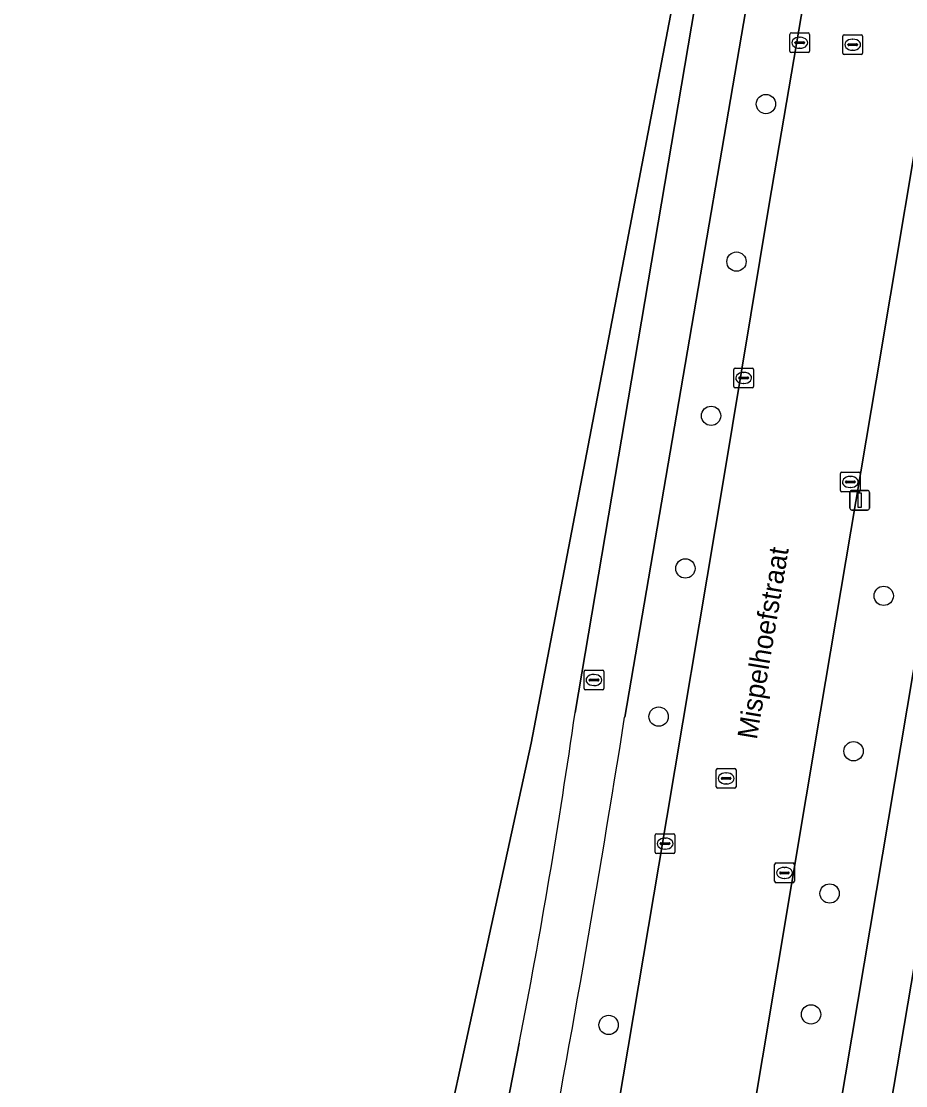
# Model space of a CAD drawing. Extents: x 156141 to 158132, y 385651 to 388333.
# Drawn here: x 156323 to 156367.7, y 386609.6 to 386663.4 of the extents above; entities that cross this region are included whole.
import ezdxf

# ---------------------------------------------------------------- set-up
doc = ezdxf.new("R2010")
doc.units = 0
for name, color, linetype in [('IMGEO_Berm_groen', 7, 'Continuous'), ('IMGEO_Boom', 7, 'Continuous'), ('IMGEO_Bouwland', 7, 'Continuous'), ('IMGEO_Fietspad_gesloten', 7, 'Continuous'), ('IMGEO_Kolk', 7, 'Continuous'), ('IMGEO_Lichtmast', 7, 'Continuous'), ('IMGEO_Openbare_ruimte_label', 7, 'Continuous'), ('IMGEO_Rijbaan_lokaal_gesloten', 7, 'Continuous'), ('IMGEO_Rioolput', 7, 'Continuous')]:
    doc.layers.add(name, color=color, linetype=linetype)

msp = doc.modelspace()

# ---------------------------------------------------------------- linework, layer by layer
at = {"layer": 'IMGEO_Berm_groen'}
for points in [[(156350.987, 386628.45), (156359.899, 386681.019), (156358.914, 386681.214), (156356.118, 386665.332), (156348.768, 386626.891), (156344.27, 386606.243), (156337.845, 386577.757), (156327.718, 386536.986), (156329.08, 386536.913), (156329.901, 386538.856), (156331.742, 386543.951), (156334.06, 386550.854), (156337.052, 386561.839), (156338.908, 386569.228), (156341.252, 386578.081), (156343.943, 386590.004), (156348.163, 386611.714)], [(156365.172, 386680.123), (156365.04, 386680.147), (156362.466, 386680.594), (156353.497, 386628.209)], [(156343.685, 386553.103), (156344.204, 386556.07), (156346.788, 386570.974), (156348.646, 386581.912), (156350.84, 386594.689), (156355.222, 386620.708), (156358.486, 386640.111), (156360.809, 386654.165), (156363.553, 386670.315), (156364.774, 386677.704), (156365.172, 386680.123)], [(156369.305, 386663.658), (156369.141, 386662.678), (156366.222, 386645.225), (156363.399, 386628.51), (156359.75, 386606.622), (156357.341, 386592.608), (156355.257, 386580.281), (156355.517, 386580.234), (156355.483, 386579.181), (156355.759, 386578.249), (156356.674, 386577.611), (156357.605, 386577.179), (156359.068, 386576.796), (156374.013, 386665.695)], [(156376.478, 386664.815), (156361.284, 386575.046)]]:
    msp.add_lwpolyline(points, dxfattribs=at)
for centre, radius, start, end in [((156028.231, 386674.305), 325.997, 348.93056, 351.91393), ((155545.833, 386756.054), 817.719, 349.208364, 351.005279)]:
    msp.add_arc(centre, radius, start, end, dxfattribs=at)
at = {"layer": 'IMGEO_Boom'}
for centre in [(156360.642, 386659.24), (156359.153, 386651.263), (156357.868, 386643.46), (156356.567, 386635.735), (156366.602, 386634.347), (156355.216, 386628.235), (156365.076, 386626.484), (156363.865, 386619.284), (156362.925, 386613.163), (156352.686, 386612.628)]:
    msp.add_circle(centre, 0.489, dxfattribs=at)
at = {"layer": 'IMGEO_Bouwland'}
msp.add_lwpolyline([(156327.718, 386536.986), (156337.845, 386577.757), (156344.27, 386606.243), (156348.768, 386626.891), (156356.118, 386665.332), (156358.914, 386681.214), (156359.797, 386685.773), (156360.143, 386687.587), (156357.465, 386688.104), (156352.633, 386690.072), (156333.91, 386700.028), (156319.754, 386708.223)], dxfattribs=at)
at = {"layer": 'IMGEO_Fietspad_gesloten'}
for points in [[(156364.735, 386706.911), (156361.044, 386687.413), (156360.703, 386685.612), (156359.899, 386681.019), (156350.987, 386628.45)], [(156353.497, 386628.209), (156362.466, 386680.594), (156363.223, 386685.205), (156367.269, 386706.451)], [(156377.323, 386685.122), (156376.063, 386677.545), (156374.013, 386665.695), (156359.068, 386576.796), (156358.828, 386575.366), (156357.806, 386569.203), (156357.464, 386566.853), (156356.663, 386561.356), (156354.926, 386551.515), (156354.742, 386549.567), (156354.24, 386545.154), (156354.117, 386544.788), (156353.91, 386544.661), (156353.548, 386544.638), (156353.12, 386544.854), (156352.234, 386545.713), (156351.908, 386546.133), (156351.166, 386547.177)], [(156360.26, 386568.995), (156361.284, 386575.046), (156376.478, 386664.815)], [(156348.163, 386611.714), (156343.943, 386590.004), (156341.252, 386578.081), (156338.908, 386569.228), (156337.052, 386561.839), (156334.06, 386550.854), (156331.742, 386543.951), (156329.901, 386538.856), (156329.08, 386536.913), (156328.367, 386535.225), (156326.447, 386529.996), (156325.935, 386528.385), (156324.936, 386524.744), (156324.596, 386523.924)]]:
    msp.add_lwpolyline(points, dxfattribs=at)
for centre, radius, start, end in [((156028.231, 386674.305), 325.997, 348.93056, 351.91393), ((155545.833, 386756.054), 817.719, 349.208364, 351.005279)]:
    msp.add_arc(centre, radius, start, end, dxfattribs=at)
at = {"layer": 'IMGEO_Kolk'}
for p, q in [((156361.929, 386662.841), (156362.781, 386662.841)), ((156361.854, 386661.915), (156361.854, 386662.767)), ((156362.113, 386662.335), (156362.113, 386662.347)), ((156362.551, 386662.298), (156362.153, 386662.298)), ((156362.156, 386662.384), (156362.554, 386662.384)), ((156362.342, 386662.621), (156362.367, 386662.621)), ((156362.597, 386662.347), (156362.597, 386662.335)), ((156362.855, 386662.767), (156362.855, 386661.915)), ((156362.781, 386661.841), (156361.929, 386661.841)), ((156362.365, 386662.061), (156362.34, 386662.061)), ((156359.016, 386644.949), (156359.016, 386645.801)), ((156359.091, 386645.875), (156359.943, 386645.875)), ((156359.504, 386645.655), (156359.529, 386645.655)), ((156360.017, 386645.801), (156360.017, 386644.949)), ((156359.275, 386645.369), (156359.275, 386645.381)), ((156359.713, 386645.332), (156359.315, 386645.332)), ((156359.318, 386645.418), (156359.716, 386645.418)), ((156359.527, 386645.095), (156359.502, 386645.095)), ((156359.759, 386645.381), (156359.759, 386645.369)), ((156359.943, 386644.875), (156359.091, 386644.875)), ((156364.412, 386639.685), (156364.412, 386640.537)), ((156364.487, 386640.611), (156365.339, 386640.611)), ((156364.9, 386640.391), (156364.925, 386640.391)), ((156365.413, 386640.537), (156365.413, 386639.685)), ((156364.671, 386640.105), (156364.671, 386640.117)), ((156365.109, 386640.068), (156364.711, 386640.068)), ((156364.714, 386640.154), (156365.112, 386640.154)), ((156364.923, 386639.831), (156364.898, 386639.831)), ((156365.155, 386640.117), (156365.155, 386640.105)), ((156365.339, 386639.611), (156364.487, 386639.611)), ((156355.041, 386621.38), (156355.041, 386622.232)), ((156355.116, 386622.306), (156355.968, 386622.306)), ((156355.529, 386622.086), (156355.554, 386622.086)), ((156356.042, 386622.232), (156356.042, 386621.38)), ((156355.3, 386621.8), (156355.3, 386621.812)), ((156355.738, 386621.763), (156355.34, 386621.763)), ((156355.343, 386621.849), (156355.741, 386621.849)), ((156355.552, 386621.526), (156355.527, 386621.526)), ((156355.784, 386621.812), (156355.784, 386621.8)), ((156355.968, 386621.306), (156355.116, 386621.306)), ((156361.154, 386620.826), (156362.006, 386620.826)), ((156361.079, 386619.9), (156361.079, 386620.752)), ((156361.338, 386620.32), (156361.338, 386620.332)), ((156361.776, 386620.283), (156361.378, 386620.283)), ((156361.381, 386620.369), (156361.779, 386620.369)), ((156361.567, 386620.606), (156361.592, 386620.606)), ((156361.822, 386620.332), (156361.822, 386620.32)), ((156362.08, 386620.752), (156362.08, 386619.9)), ((156362.006, 386619.826), (156361.154, 386619.826)), ((156361.59, 386620.046), (156361.565, 386620.046))]:
    msp.add_line(p, q, dxfattribs=at)
for points in [[(156361.929, 386662.841), (156362.781, 386662.841)], [(156361.854, 386661.915), (156361.854, 386662.767)], [(156362.855, 386662.767), (156362.855, 386661.915)], [(156362.781, 386661.841), (156361.929, 386661.841)], [(156359.016, 386644.949), (156359.016, 386645.801)], [(156359.091, 386645.875), (156359.943, 386645.875)], [(156360.017, 386645.801), (156360.017, 386644.949)], [(156359.943, 386644.875), (156359.091, 386644.875)], [(156364.412, 386639.685), (156364.412, 386640.537)], [(156364.487, 386640.611), (156365.339, 386640.611)], [(156365.413, 386640.537), (156365.413, 386639.685)], [(156365.339, 386639.611), (156364.487, 386639.611)], [(156355.041, 386621.38), (156355.041, 386622.232)], [(156355.116, 386622.306), (156355.968, 386622.306)], [(156356.042, 386622.232), (156356.042, 386621.38)], [(156355.968, 386621.306), (156355.116, 386621.306)], [(156361.154, 386620.826), (156362.006, 386620.826)], [(156361.079, 386619.9), (156361.079, 386620.752)], [(156362.08, 386620.752), (156362.08, 386619.9)], [(156362.006, 386619.826), (156361.154, 386619.826)]]:
    msp.add_lwpolyline(points, dxfattribs=at)
for centre, radius, start, end in [((156361.931, 386662.765), 0.0765, 91.552, 178.448), ((156361.931, 386662.765), 0.0765, 91.552, 178.448), ((156362.779, 386662.765), 0.0765, 1.552, 88.448), ((156362.779, 386662.765), 0.0765, 1.552, 88.448), ((156362.153, 386662.344), 0.0403, 85.8775, 175.7526), ((156362.15, 386662.334), 0.0366, 178.938, 274.7102), ((156362.554, 386662.341), 0.043, 264.8664, 352.4533), ((156362.558, 386662.346), 0.0386, 1.7309, 96.639), ((156361.931, 386661.917), 0.0765, 181.552, 268.448), ((156361.931, 386661.917), 0.0765, 181.552, 268.448), ((156362.779, 386661.917), 0.0765, 271.552, 358.448), ((156362.779, 386661.917), 0.0765, 271.552, 358.448), ((156359.093, 386645.799), 0.0765, 91.552, 178.448), ((156359.093, 386645.799), 0.0765, 91.552, 178.448), ((156359.941, 386645.799), 0.0765, 1.552, 88.448), ((156359.941, 386645.799), 0.0765, 1.552, 88.448), ((156359.315, 386645.378), 0.0403, 85.8775, 175.7526), ((156359.312, 386645.368), 0.0366, 178.938, 274.7102), ((156359.716, 386645.375), 0.043, 264.8664, 352.4533), ((156359.72, 386645.38), 0.0386, 1.7309, 96.639), ((156359.093, 386644.951), 0.0765, 181.552, 268.448), ((156359.093, 386644.951), 0.0765, 181.552, 268.448), ((156359.941, 386644.951), 0.0765, 271.552, 358.448), ((156359.941, 386644.951), 0.0765, 271.552, 358.448), ((156364.489, 386640.535), 0.0765, 91.552, 178.448), ((156364.489, 386640.535), 0.0765, 91.552, 178.448), ((156365.337, 386640.535), 0.0765, 1.552, 88.448), ((156365.337, 386640.535), 0.0765, 1.552, 88.448), ((156364.489, 386639.687), 0.0765, 181.552, 268.448), ((156364.489, 386639.687), 0.0765, 181.552, 268.448), ((156364.711, 386640.114), 0.0403, 85.8775, 175.7526), ((156364.708, 386640.104), 0.0366, 178.938, 274.7102), ((156365.112, 386640.111), 0.043, 264.8664, 352.4533), ((156365.116, 386640.116), 0.0386, 1.7309, 96.639), ((156365.337, 386639.687), 0.0765, 271.552, 358.448), ((156365.337, 386639.687), 0.0765, 271.552, 358.448), ((156355.118, 386622.23), 0.0765, 91.552, 178.448), ((156355.118, 386622.23), 0.0765, 91.552, 178.448), ((156355.966, 386622.23), 0.0765, 1.552, 88.448), ((156355.966, 386622.23), 0.0765, 1.552, 88.448), ((156355.118, 386621.382), 0.0765, 181.552, 268.448), ((156355.118, 386621.382), 0.0765, 181.552, 268.448), ((156355.34, 386621.809), 0.0403, 85.8775, 175.7526), ((156355.337, 386621.799), 0.0366, 178.938, 274.7102), ((156355.741, 386621.806), 0.043, 264.8664, 352.4533), ((156355.745, 386621.811), 0.0386, 1.7309, 96.639), ((156355.966, 386621.382), 0.0765, 271.552, 358.448), ((156355.966, 386621.382), 0.0765, 271.552, 358.448), ((156361.156, 386620.75), 0.0765, 91.552, 178.448), ((156361.156, 386620.75), 0.0765, 91.552, 178.448), ((156362.004, 386620.75), 0.0765, 1.552, 88.448), ((156362.004, 386620.75), 0.0765, 1.552, 88.448), ((156361.378, 386620.329), 0.0403, 85.8775, 175.7526), ((156361.375, 386620.319), 0.0366, 178.938, 274.7102), ((156361.779, 386620.326), 0.043, 264.8664, 352.4533), ((156361.783, 386620.331), 0.0386, 1.7309, 96.639), ((156361.156, 386619.902), 0.0765, 181.552, 268.448), ((156361.156, 386619.902), 0.0765, 181.552, 268.448), ((156362.004, 386619.902), 0.0765, 271.552, 358.448), ((156362.004, 386619.902), 0.0765, 271.552, 358.448)]:
    msp.add_arc(centre, radius, start, end, dxfattribs=at)
for centre, major_axis, ratio, start_param, end_param in [((156362.341, 386662.341), (-0.387, 0.002), 0.722429, 4.712389, 7.853982), ((156362.366, 386662.341), (-0.39, 0.002), 0.717154, 1.570796, 4.712389), ((156359.503, 386645.375), (-0.387, 0.002), 0.722429, 4.712389, 7.853982), ((156359.528, 386645.375), (-0.39, 0.002), 0.717154, 1.570796, 4.712389), ((156364.899, 386640.111), (-0.387, 0.002), 0.722429, 4.712389, 7.853982), ((156364.924, 386640.111), (-0.39, 0.002), 0.717154, 1.570796, 4.712389), ((156355.528, 386621.806), (-0.387, 0.002), 0.722429, 4.712389, 7.853982), ((156355.553, 386621.806), (-0.39, 0.002), 0.717154, 1.570796, 4.712389), ((156361.566, 386620.326), (-0.387, 0.002), 0.722429, 4.712389, 7.853982), ((156361.591, 386620.326), (-0.39, 0.002), 0.717154, 1.570796, 4.712389)]:
    msp.add_ellipse(centre, major_axis=major_axis, ratio=ratio, start_param=start_param, end_param=end_param, dxfattribs=at)
at = {"layer": 'IMGEO_Lichtmast'}
for p, q in [((156364.99, 386639.686), (156365.78, 386639.686)), ((156365.78, 386639.686), (156364.99, 386639.686)), ((156364.89, 386638.786), (156364.89, 386639.586)), ((156364.89, 386639.586), (156364.89, 386638.786)), ((156365.88, 386639.586), (156365.88, 386638.786)), ((156365.88, 386638.786), (156365.88, 386639.586)), ((156365.78, 386638.686), (156364.99, 386638.686)), ((156364.99, 386638.686), (156365.78, 386638.686))]:
    msp.add_line(p, q, dxfattribs=at)
msp.add_lwpolyline([(156365.31, 386639.561), (156365.46, 386639.561), (156365.46, 386638.811), (156365.31, 386638.811), (156365.31, 386639.561)], dxfattribs=at)
for centre, start, end in [((156364.99, 386639.586), 90, 180), ((156364.99, 386639.586), 90, 180), ((156365.78, 386639.586), 0, 90), ((156365.78, 386639.586), 360, 90), ((156364.99, 386638.786), 180, 270), ((156364.99, 386638.786), 180, 270), ((156365.78, 386638.786), 270, 0), ((156365.78, 386638.786), 270, 0)]:
    msp.add_arc(centre, 0.1, start, end, dxfattribs=at)
at = {"layer": 'IMGEO_Rijbaan_lokaal_gesloten'}
for points in [[(156366.226, 386686.353), (156365.933, 386684.725), (156365.886, 386684.463), (156365.172, 386680.123), (156364.774, 386677.704), (156363.553, 386670.315), (156360.809, 386654.165), (156358.486, 386640.111), (156355.222, 386620.708), (156350.84, 386594.689), (156348.646, 386581.912), (156346.788, 386570.974), (156344.204, 386556.07), (156343.685, 386553.103)], [(156355.014, 386578.858), (156355.161, 386579.716), (156355.257, 386580.281), (156357.341, 386592.608), (156359.75, 386606.622), (156363.399, 386628.51), (156366.222, 386645.225), (156369.141, 386662.678), (156369.305, 386663.658), (156371.343, 386675.841), (156372.272, 386681.317), (156372.444, 386682.329), (156373.065, 386686.117)]]:
    msp.add_lwpolyline(points, dxfattribs=at)
at = {"layer": 'IMGEO_Rioolput'}
for p, q in [((156364.533, 386661.818), (156364.533, 386662.67)), ((156364.608, 386662.744), (156365.46, 386662.744)), ((156364.835, 386662.287), (156365.233, 386662.287)), ((156365.021, 386662.524), (156365.046, 386662.524)), ((156365.534, 386662.67), (156365.534, 386661.818)), ((156365.46, 386661.744), (156364.608, 386661.744)), ((156364.792, 386662.238), (156364.792, 386662.25)), ((156365.23, 386662.201), (156364.832, 386662.201)), ((156365.044, 386661.964), (156365.019, 386661.964)), ((156365.276, 386662.25), (156365.276, 386662.238)), ((156351.443, 386629.662), (156351.443, 386630.514)), ((156351.518, 386630.588), (156352.37, 386630.588)), ((156352.444, 386630.514), (156352.444, 386629.662)), ((156351.702, 386630.082), (156351.702, 386630.094)), ((156352.14, 386630.045), (156351.742, 386630.045)), ((156351.745, 386630.131), (156352.143, 386630.131)), ((156351.931, 386630.368), (156351.956, 386630.368)), ((156352.186, 386630.094), (156352.186, 386630.082)), ((156352.37, 386629.588), (156351.518, 386629.588)), ((156351.954, 386629.808), (156351.929, 386629.808)), ((156358.129, 386624.682), (156358.129, 386625.534)), ((156358.204, 386625.608), (156359.056, 386625.608)), ((156358.388, 386625.102), (156358.388, 386625.114)), ((156358.431, 386625.151), (156358.829, 386625.151)), ((156358.617, 386625.388), (156358.642, 386625.388)), ((156358.872, 386625.114), (156358.872, 386625.102)), ((156359.13, 386625.534), (156359.13, 386624.682)), ((156359.056, 386624.608), (156358.204, 386624.608)), ((156358.826, 386625.065), (156358.428, 386625.065)), ((156358.64, 386624.828), (156358.615, 386624.828))]:
    msp.add_line(p, q, dxfattribs=at)
for points in [[(156364.533, 386661.818), (156364.533, 386662.67)], [(156364.608, 386662.744), (156365.46, 386662.744)], [(156365.534, 386662.67), (156365.534, 386661.818)], [(156365.46, 386661.744), (156364.608, 386661.744)], [(156351.443, 386629.662), (156351.443, 386630.514)], [(156351.518, 386630.588), (156352.37, 386630.588)], [(156352.444, 386630.514), (156352.444, 386629.662)], [(156352.37, 386629.588), (156351.518, 386629.588)], [(156358.129, 386624.682), (156358.129, 386625.534)], [(156358.204, 386625.608), (156359.056, 386625.608)], [(156359.13, 386625.534), (156359.13, 386624.682)], [(156359.056, 386624.608), (156358.204, 386624.608)]]:
    msp.add_lwpolyline(points, dxfattribs=at)
for centre, radius, start, end in [((156364.61, 386662.668), 0.0765, 91.552, 178.448), ((156364.61, 386662.668), 0.0765, 91.552, 178.448), ((156364.832, 386662.247), 0.0403, 85.8775, 175.7526), ((156365.237, 386662.249), 0.0386, 1.7309, 96.639), ((156365.458, 386662.668), 0.0765, 1.552, 88.448), ((156365.458, 386662.668), 0.0765, 1.552, 88.448), ((156364.61, 386661.82), 0.0765, 181.552, 268.448), ((156364.61, 386661.82), 0.0765, 181.552, 268.448), ((156364.829, 386662.237), 0.0366, 178.938, 274.7102), ((156365.233, 386662.244), 0.043, 264.8664, 352.4533), ((156365.458, 386661.82), 0.0765, 271.552, 358.448), ((156365.458, 386661.82), 0.0765, 271.552, 358.448), ((156351.52, 386630.512), 0.0765, 91.552, 178.448), ((156351.52, 386630.512), 0.0765, 91.552, 178.448), ((156352.368, 386630.512), 0.0765, 1.552, 88.448), ((156352.368, 386630.512), 0.0765, 1.552, 88.448), ((156351.742, 386630.091), 0.0403, 85.8775, 175.7526), ((156351.739, 386630.081), 0.0366, 178.938, 274.7102), ((156352.143, 386630.088), 0.043, 264.8664, 352.4533), ((156352.147, 386630.093), 0.0386, 1.7309, 96.639), ((156351.52, 386629.664), 0.0765, 181.552, 268.448), ((156351.52, 386629.664), 0.0765, 181.552, 268.448), ((156352.368, 386629.664), 0.0765, 271.552, 358.448), ((156352.368, 386629.664), 0.0765, 271.552, 358.448), ((156358.206, 386625.532), 0.0765, 91.552, 178.448), ((156358.206, 386625.532), 0.0765, 91.552, 178.448), ((156358.428, 386625.111), 0.0403, 85.8775, 175.7526), ((156358.425, 386625.101), 0.0366, 178.938, 274.7102), ((156358.829, 386625.108), 0.043, 264.8664, 352.4533), ((156358.833, 386625.113), 0.0386, 1.7309, 96.639), ((156359.054, 386625.532), 0.0765, 1.552, 88.448), ((156359.054, 386625.532), 0.0765, 1.552, 88.448), ((156358.206, 386624.684), 0.0765, 181.552, 268.448), ((156358.206, 386624.684), 0.0765, 181.552, 268.448), ((156359.054, 386624.684), 0.0765, 271.552, 358.448), ((156359.054, 386624.684), 0.0765, 271.552, 358.448)]:
    msp.add_arc(centre, radius, start, end, dxfattribs=at)
for centre, major_axis, ratio, start_param, end_param in [((156365.02, 386662.244), (-0.387, 0.002), 0.722429, 4.712389, 7.853982), ((156365.045, 386662.244), (-0.39, 0.002), 0.717154, 1.570796, 4.712389), ((156351.93, 386630.088), (-0.387, 0.002), 0.722429, 4.712389, 7.853982), ((156351.955, 386630.088), (-0.39, 0.002), 0.717154, 1.570796, 4.712389), ((156358.616, 386625.108), (-0.387, 0.002), 0.722429, 4.712389, 7.853982), ((156358.641, 386625.108), (-0.39, 0.002), 0.717154, 1.570796, 4.712389)]:
    msp.add_ellipse(centre, major_axis=major_axis, ratio=ratio, start_param=start_param, end_param=end_param, dxfattribs=at)

# ---------------------------------------------------------------- texts
at = {"layer": 'IMGEO_Openbare_ruimte_label'}
msp.add_text('Mispelhoefstraat', height=1, rotation=80.5, dxfattribs=at).set_placement((156360.179, 386627.043))

doc.saveas('drawing.dxf')
